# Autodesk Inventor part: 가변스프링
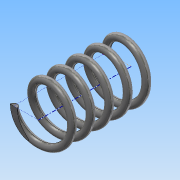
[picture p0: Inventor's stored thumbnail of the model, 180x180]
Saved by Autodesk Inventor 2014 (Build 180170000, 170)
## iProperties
Created: 2019-10
Part Number: 가변스프링
Material: 스테인레스 스틸
Document SubType Name: Modeling
Designer: net
Density: 8.08 g/cm^3
Appearance: 반연마
Mass: 147.864 g
Surface Area: 124.194 cm^2
Volume: 18.3 cm^3
Author: net
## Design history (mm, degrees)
sketch "스케치1"
  geometry: L1 (0, 0)-(-21, 0); L2 (-21, 0)-(-21, 67.25); L3 (-21, 67.25)-(0, 67.25); L4 (0, 67.25)-(0, 0); C1 r 3 at (-21, 67.25)
  constraints: 8 end point, 2 parallel, 1 centre point, 1 coincident, 1 horizontal, 1 perpendicular
  dimensions: "d0" = 6 diameter of C1; "d1" = 42 diameter of L2 L4; "d2" = 67.25 distance of L3.end L1.start (derived)
feature "코일1" sketch "스케치1" pitch "d3" = 10; turns "d5" = 5; dims "d4" = 67.25 (= d2), "d6" = 0, angle "d7" = 90 deg, angle "d8" = 90 deg, "d9" = 0, "d10" = 0
node "작업 평면1"
sketch "스케치2"
  geometry: L1 (3, 0)-(-3, 0) reference; 1 further point
  constraints: 1 horizontal alignment
extrude "돌출1" cut sketch "스케치2" distance "d11" = 10; taper "d12" = 0 deg
sketch "스케치3"
  geometry: L1 (18, 0)-(24, 0) reference; 1 further point
  constraints: 1 horizontal alignment
extrude "돌출2" cut sketch "스케치3" distance "d13" = 10; taper "d14" = 0 deg
node "솔리드1"
node "절단 모서리 투영1"
node "절단 모서리 투영2"
